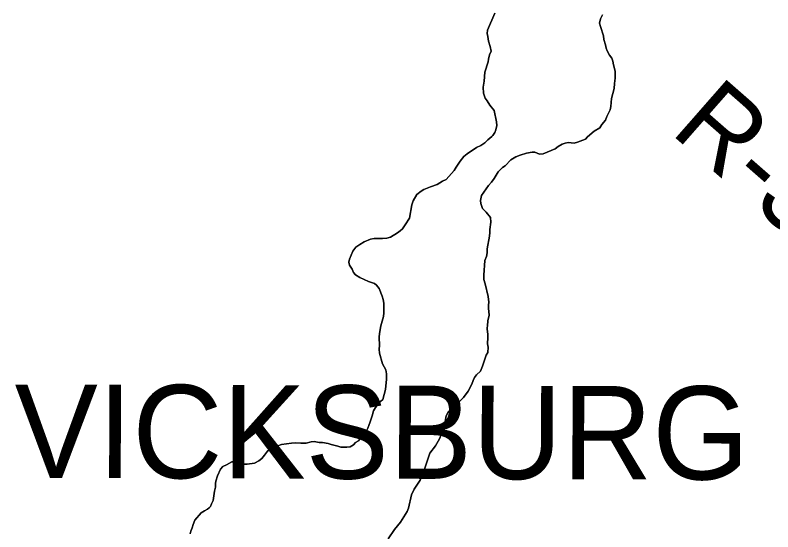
# Model space of a CAD drawing. Extents: x 3172297 to 3210190, y 958463 to 983887.
# Drawn here: x 3190075 to 3190887, y 964550 to 965104 of the extents above; entities that cross this region are included whole.
import ezdxf

# ---------------------------------------------------------------- set-up
doc = ezdxf.new("R2010")
doc.units = 0
for name, color, linetype in [('V-RIVR-RANG-IDEN', 7, 'Continuous'), ('V-SITE-VEGE', 7, 'Continuous'), ('V-TOPO-GNAM-IDEN', 7, 'Continuous'), ('V-TOPO-SHOR', 7, 'Continuous')]:
    doc.layers.add(name, color=color, linetype=linetype)

msp = doc.modelspace()

# ---------------------------------------------------------------- linework, layer by layer
at = {"layer": 'V-SITE-VEGE'}
for p, q in [((3190589.23, 965106.31), (3190581.36, 965088.03)), ((3190701.2, 965095.65), (3190702.22, 965100.13)), ((3190702.22, 965100.13), (3190704.62, 965104.62)), ((3190702.25, 965091.86), (3190701.2, 965095.65)), ((3190705.73, 965081.89), (3190702.25, 965091.86)), ((3190581.36, 965088.03), (3190581.03, 965084.58)), ((3190581.03, 965084.58), (3190581.73, 965081.14)), ((3190581.73, 965081.14), (3190582.44, 965076.32)), ((3190582.44, 965076.32), (3190584.18, 965070.47)), ((3190706.08, 965078.1), (3190705.73, 965081.89)), ((3190707.82, 965072.25), (3190706.08, 965078.1)), ((3190584.18, 965070.47), (3190585.22, 965065.65)), ((3190708.52, 965068.81), (3190707.82, 965072.25)), ((3190709.57, 965065.71), (3190708.52, 965068.81)), ((3190583.51, 965061.51), (3190582.15, 965057.03)), ((3190585.22, 965065.65), (3190583.51, 965061.51)), ((3190711.99, 965061.24), (3190709.57, 965065.71)), ((3190714.41, 965058.15), (3190711.99, 965061.24)), ((3190581.82, 965053.93), (3190578.41, 965042.89)), ((3190582.15, 965057.03), (3190581.82, 965053.93)), ((3190715.46, 965054.71), (3190714.41, 965058.15)), ((3190716.16, 965050.92), (3190715.46, 965054.71)), ((3190717.91, 965044.04), (3190716.16, 965050.92)), ((3190578.41, 965042.89), (3190577.75, 965033.25)), ((3190717.93, 965036.46), (3190717.91, 965044.04)), ((3190717.26, 965030.94), (3190717.93, 965036.46)), ((3190577.75, 965033.25), (3190576.74, 965027.05)), ((3190576.74, 965027.05), (3190577.1, 965020.5)), ((3190716.93, 965025.44), (3190717.26, 965030.94)), ((3190577.1, 965020.5), (3190578.85, 965015)), ((3190714.21, 965014.75), (3190716.93, 965025.44)), ((3190578.85, 965015), (3190580.92, 965012.25)), ((3190580.92, 965012.25), (3190583.69, 965007.43)), ((3190713.55, 965006.14), (3190714.21, 965014.75)), ((3190583.69, 965007.43), (3190588.53, 965001.94)), ((3190709.11, 964995.44), (3190712.53, 965002.69)), ((3190712.53, 965002.69), (3190713.55, 965006.14)), ((3190588.53, 965001.94), (3190590.98, 964989.89)), ((3190707.74, 964991.65), (3190709.11, 964995.44)), ((3190590.98, 964989.89), (3190591.34, 964985.76)), ((3190701.57, 964983.36), (3190703.62, 964986.81)), ((3190703.62, 964986.81), (3190707.74, 964991.65)), ((3190588.95, 964978.17), (3190586.9, 964975.07)), ((3190590.32, 964981.28), (3190588.95, 964978.17)), ((3190591.34, 964985.76), (3190590.32, 964981.28)), ((3190688.51, 964973.68), (3190695.38, 964979.9)), ((3190695.38, 964979.9), (3190701.57, 964983.36)), ((3190581.75, 964970.57), (3190578.31, 964967.12)), ((3190585.87, 964974.03), (3190581.75, 964970.57)), ((3190586.9, 964975.07), (3190585.87, 964974.03)), ((3190680.6, 964969.17), (3190686.11, 964971.26)), ((3190686.11, 964971.26), (3190688.51, 964973.68)), ((3190569.37, 964962.27), (3190559.41, 964955.34)), ((3190574.19, 964964.35), (3190569.37, 964962.27)), ((3190578.31, 964967.12), (3190574.19, 964964.35)), ((3190653.77, 964960.82), (3190656.85, 964963.24)), ((3190656.85, 964963.24), (3190661.33, 964965.66)), ((3190661.33, 964965.66), (3190664.42, 964966.71)), ((3190664.42, 964966.71), (3190667.52, 964967.41)), ((3190667.52, 964967.41), (3190674.07, 964966.74)), ((3190674.07, 964966.74), (3190677.85, 964967.79)), ((3190677.85, 964967.79), (3190680.6, 964969.17)), ((3190559.41, 964955.34), (3190555.97, 964952.58)), ((3190611.43, 964952.07), (3190616.24, 964954.15)), ((3190616.24, 964954.15), (3190623.12, 964956.24)), ((3190623.12, 964956.24), (3190628.98, 964957.29)), ((3190628.98, 964957.29), (3190632.08, 964957.3)), ((3190632.08, 964957.3), (3190636.91, 964954.91)), ((3190636.91, 964954.91), (3190641.04, 964955.61)), ((3190641.04, 964955.61), (3190653.77, 964960.82)), ((3190551.85, 964947.4), (3190547.74, 964941.18)), ((3190555.97, 964952.58), (3190551.85, 964947.4)), ((3190600.09, 964942.73), (3190606.27, 964948.95)), ((3190606.27, 964948.95), (3190611.43, 964952.07)), ((3190545.69, 964937.39), (3190537.1, 964928.06)), ((3190547.74, 964941.18), (3190545.69, 964937.39)), ((3190592.53, 964936.16), (3190597.34, 964940.66)), ((3190597.34, 964940.66), (3190600.09, 964942.73)), ((3190588.42, 964928.92), (3190592.53, 964936.16)), ((3190527.14, 964922.52), (3190520.25, 964920.08)), ((3190532.98, 964925.98), (3190527.14, 964922.52)), ((3190537.1, 964928.06), (3190532.98, 964925.98)), ((3190574.71, 964910.62), (3190582.25, 964921.32)), ((3190582.25, 964921.32), (3190585.68, 964925.12)), ((3190585.68, 964925.12), (3190588.42, 964928.92)), ((3190510.28, 964915.57), (3190505.47, 964911.77)), ((3190513.03, 964917.3), (3190510.28, 964915.57)), ((3190520.25, 964920.08), (3190513.03, 964917.3)), ((3190501.7, 964904.87), (3190500, 964900.73)), ((3190505.47, 964911.77), (3190501.7, 964904.87)), ((3190573.69, 964905.45), (3190574.71, 964910.62)), ((3190574.04, 964902.35), (3190573.69, 964905.45)), ((3190500, 964900.73), (3190497.63, 964886.6)), ((3190575.79, 964896.84), (3190574.04, 964902.35)), ((3190579.93, 964892.72), (3190575.79, 964896.84)), ((3190584.43, 964887.23), (3190579.93, 964892.72)), ((3190497.63, 964886.6), (3190493.18, 964879.35)), ((3190583.78, 964874.48), (3190584.79, 964882.06)), ((3190584.79, 964882.06), (3190584.43, 964887.23)), ((3190487.68, 964872.79), (3190484.94, 964870.71)), ((3190490.09, 964874.86), (3190487.68, 964872.79)), ((3190493.18, 964879.35), (3190490.09, 964874.86)), ((3190583.79, 964871.03), (3190583.78, 964874.48)), ((3190455.68, 964864.07), (3190449.15, 964860.95)), ((3190459.81, 964864.78), (3190455.68, 964864.07)), ((3190468.77, 964864.81), (3190459.81, 964864.78)), ((3190473.24, 964865.17), (3190468.77, 964864.81)), ((3190477.37, 964866.21), (3190473.24, 964865.17)), ((3190484.94, 964870.71), (3190477.37, 964866.21)), ((3190580.75, 964853.46), (3190583.46, 964867.24)), ((3190583.46, 964867.24), (3190583.79, 964871.03)), ((3190444.33, 964858.18), (3190440.21, 964855.41)), ((3190449.15, 964860.95), (3190444.33, 964858.18)), ((3190436.78, 964850.93), (3190433.36, 964842.65)), ((3190440.21, 964855.41), (3190436.78, 964850.93)), ((3190580.08, 964845.54), (3190580.76, 964849.33)), ((3190580.76, 964849.33), (3190580.75, 964853.46)), ((3190433.36, 964842.65), (3190432.68, 964839.2)), ((3190577.4, 964825.2), (3190578.38, 964841.05)), ((3190578.38, 964841.05), (3190580.08, 964845.54)), ((3190432.68, 964839.2), (3190433.38, 964836.1)), ((3190433.38, 964836.1), (3190436.15, 964831.63)), ((3190436.15, 964831.63), (3190437.54, 964828.19)), ((3190437.54, 964828.19), (3190439.62, 964825.79)), ((3190439.62, 964825.79), (3190444.45, 964822.71)), ((3190577.41, 964820.72), (3190577.4, 964825.2)), ((3190444.45, 964822.71), (3190453.76, 964818.6)), ((3190453.76, 964818.6), (3190459.97, 964816.55)), ((3190459.97, 964816.55), (3190462.39, 964814.49)), ((3190578.8, 964815.91), (3190577.41, 964820.72)), ((3190581.95, 964802.49), (3190578.8, 964815.91)), ((3190462.39, 964814.49), (3190465.15, 964811.06)), ((3190465.15, 964811.06), (3190468.28, 964802.8)), ((3190468.28, 964802.8), (3190469.32, 964799.36)), ((3190469.32, 964799.36), (3190470.02, 964795.23)), ((3190582.66, 964796.29), (3190581.95, 964802.49)), ((3190470.02, 964795.23), (3190470.06, 964784.9)), ((3190582.32, 964793.19), (3190582.66, 964796.29)), ((3190582.33, 964790.09), (3190582.32, 964793.19)), ((3190470.06, 964784.9), (3190469.73, 964781.11)), ((3190583.04, 964782.51), (3190582.33, 964790.09)), ((3190469.73, 964781.11), (3190467, 964771.11)), ((3190581.36, 964771.14), (3190581.69, 964776.31)), ((3190581.69, 964776.31), (3190583.04, 964782.51)), ((3190467, 964771.11), (3190465.65, 964762.84)), ((3190581.02, 964769.07), (3190581.36, 964771.14)), ((3190581.03, 964767.69), (3190581.02, 964769.07)), ((3190581.73, 964761.84), (3190581.03, 964767.69)), ((3190465.65, 964762.84), (3190465.32, 964759.05)), ((3190465.32, 964759.05), (3190465.35, 964750.1)), ((3190581.75, 964758.4), (3190581.73, 964761.84)), ((3190581.08, 964751.85), (3190581.75, 964758.4)), ((3190581.78, 964748.06), (3190581.08, 964751.85)), ((3190465.35, 964750.1), (3190465.02, 964745.96)), ((3190465.02, 964745.96), (3190465.38, 964741.83)), ((3190579.74, 964739.44), (3190581.45, 964742.55)), ((3190581.45, 964742.55), (3190581.78, 964748.06)), ((3190465.38, 964741.83), (3190468.86, 964730.48)), ((3190575.99, 964727.72), (3190579.74, 964739.44)), ((3190468.86, 964730.48), (3190472.32, 964723.94)), ((3190573.6, 964722.55), (3190575.99, 964727.72)), ((3190472.32, 964723.94), (3190473.03, 964719.47)), ((3190473.03, 964719.47), (3190473.04, 964713.95)), ((3190567.42, 964715.64), (3190569.48, 964718.4)), ((3190569.48, 964718.4), (3190573.6, 964722.55)), ((3190473.04, 964713.95), (3190472.05, 964702.93)), ((3190564.34, 964708.39), (3190565.71, 964712.53)), ((3190565.71, 964712.53), (3190567.42, 964715.64)), ((3190472.05, 964702.93), (3190470.34, 964697.41)), ((3190560.57, 964701.15), (3190564.34, 964708.39)), ((3190470.34, 964697.41), (3190468.98, 964691.9)), ((3190547.19, 964685.95), (3190555.43, 964694.24)), ((3190555.43, 964694.24), (3190560.57, 964701.15)), ((3190466.58, 964689.82), (3190461.09, 964683.6)), ((3190468.98, 964691.9), (3190466.58, 964689.82)), ((3190543.07, 964682.49), (3190547.19, 964685.95)), ((3190459.04, 964679.81), (3190457.67, 964674.64)), ((3190461.09, 964683.6), (3190459.04, 964679.81)), ((3190536.9, 964674.55), (3190539.29, 964679.04)), ((3190539.29, 964679.04), (3190543.07, 964682.49)), ((3190457.67, 964674.64), (3190455.63, 964668.09)), ((3190535.55, 964665.59), (3190536.22, 964670.76)), ((3190536.22, 964670.76), (3190536.9, 964674.55)), ((3190452.9, 964661.19), (3190449.81, 964654.98)), ((3190453.92, 964664.29), (3190452.9, 964661.19)), ((3190455.63, 964668.09), (3190453.92, 964664.29)), ((3190532.82, 964656.97), (3190534.53, 964661.8)), ((3190534.53, 964661.8), (3190535.55, 964665.59)), ((3190449.81, 964654.98), (3190443.98, 964649.1)), ((3190529.74, 964650.07), (3190531.45, 964654.21)), ((3190531.45, 964654.21), (3190532.82, 964656.97)), ((3190371.31, 964645.42), (3190360.3, 964643.66)), ((3190375.79, 964645.78), (3190371.31, 964645.42)), ((3190381.3, 964645.11), (3190375.79, 964645.78)), ((3190386.81, 964645.13), (3190381.3, 964645.11)), ((3190392.32, 964646.52), (3190386.81, 964645.13)), ((3190395.42, 964646.88), (3190392.32, 964646.52)), ((3190400.93, 964645.86), (3190395.42, 964646.88)), ((3190404.38, 964645.88), (3190400.93, 964645.86)), ((3190410.58, 964644.86), (3190404.38, 964645.88)), ((3190413.68, 964643.84), (3190410.58, 964644.86)), ((3190439.85, 964645.99), (3190437.8, 964643.57)), ((3190442.95, 964647.72), (3190439.85, 964645.99)), ((3190443.98, 964649.1), (3190442.95, 964647.72)), ((3190525.63, 964642.48), (3190529.74, 964650.07)), ((3190345.51, 964636.73), (3190342.42, 964632.24)), ((3190348.26, 964638.8), (3190345.51, 964636.73)), ((3190351.35, 964639.85), (3190348.26, 964638.8)), ((3190356.51, 964642.28), (3190351.35, 964639.85)), ((3190360.3, 964643.66), (3190356.51, 964642.28)), ((3190420.92, 964642.14), (3190413.68, 964643.84)), ((3190424.03, 964641.12), (3190420.92, 964642.14)), ((3190427.47, 964641.13), (3190424.03, 964641.12)), ((3190430.57, 964640.79), (3190427.47, 964641.13)), ((3190434.01, 964641.15), (3190430.57, 964640.79)), ((3190437.8, 964643.57), (3190434.01, 964641.15)), ((3190519.46, 964634.54), (3190525.63, 964642.48)), ((3190339.33, 964628.78), (3190336.24, 964626.37)), ((3190342.42, 964632.24), (3190339.33, 964628.78)), ((3190515.36, 964622.82), (3190519.46, 964634.54)), ((3190301.47, 964622.12), (3190297.68, 964620.38)), ((3190307.31, 964625.23), (3190301.47, 964622.12)), ((3190310.41, 964625.25), (3190307.31, 964625.23)), ((3190315.24, 964624.23), (3190310.41, 964625.25)), ((3190319.38, 964622.87), (3190315.24, 964624.23)), ((3190323.85, 964622.88), (3190319.38, 964622.87)), ((3190331.43, 964623.94), (3190323.85, 964622.88)), ((3190336.24, 964626.37), (3190331.43, 964623.94)), ((3190512.3, 964612.81), (3190515.36, 964622.82)), ((3190294.94, 964617.28), (3190291.86, 964610.38)), ((3190297.68, 964620.38), (3190294.94, 964617.28)), ((3190510.93, 964609.36), (3190512.3, 964612.81)), ((3190290.16, 964604.52), (3190289.82, 964602.1)), ((3190291.86, 964610.38), (3190290.16, 964604.52)), ((3190502.71, 964595.91), (3190509.22, 964605.57)), ((3190509.22, 964605.57), (3190510.93, 964609.36)), ((3190289.83, 964597.97), (3190288.81, 964593.83)), ((3190289.82, 964602.1), (3190289.83, 964597.97)), ((3190288.81, 964593.83), (3190287.12, 964583.84)), ((3190496.57, 964575.56), (3190499.97, 964590.04)), ((3190499.97, 964590.04), (3190502.71, 964595.91)), ((3190285.41, 964580.39), (3190284.39, 964577.29)), ((3190287.12, 964583.84), (3190285.41, 964580.39)), ((3190277.86, 964572.79), (3190274.42, 964570.71)), ((3190281.3, 964574.52), (3190277.86, 964572.79)), ((3190283.02, 964575.9), (3190281.3, 964574.52)), ((3190284.39, 964577.29), (3190283.02, 964575.9)), ((3190488.01, 964560.72), (3190495.21, 964572.11)), ((3190495.21, 964572.11), (3190496.57, 964575.56)), ((3190274.42, 964570.71), (3190267.56, 964562.76)), ((3190265.85, 964557.94), (3190264.83, 964554.49)), ((3190267.56, 964562.76), (3190265.85, 964557.94)), ((3190481.49, 964552.78), (3190484.92, 964556.58)), ((3190484.92, 964556.58), (3190488.01, 964560.72)), ((3190263.46, 964551.04), (3190262.44, 964547.94)), ((3190264.83, 964554.49), (3190263.46, 964551.04)), ((3190474.63, 964542.77), (3190481.49, 964552.78))]:
    msp.add_line(p, q, dxfattribs=at)
at = {"layer": 'V-TOPO-SHOR'}
for points in [[(3190582.15, 965057.03), (3190583.51, 965061.51), (3190585.22, 965065.65), (3190584.18, 965070.47), (3190582.44, 965076.32), (3190581.73, 965081.14), (3190581.03, 965084.58), (3190581.36, 965088.03), (3190589.23, 965106.31)], [(3190704.62, 965104.62), (3190702.22, 965100.13), (3190701.2, 965095.65), (3190702.25, 965091.86), (3190705.73, 965081.89), (3190706.08, 965078.1), (3190707.82, 965072.25), (3190708.52, 965068.81), (3190709.57, 965065.71), (3190711.99, 965061.24), (3190714.41, 965058.15), (3190715.46, 965054.71), (3190716.16, 965050.92), (3190717.91, 965044.04), (3190717.93, 965036.46), (3190717.26, 965030.95), (3190716.93, 965025.44), (3190714.21, 965014.75), (3190713.55, 965006.14), (3190712.53, 965002.69), (3190709.11, 964995.44), (3190707.74, 964991.65), (3190703.62, 964986.81), (3190701.57, 964983.36), (3190695.38, 964979.9), (3190688.51, 964973.68), (3190686.11, 964971.26), (3190680.6, 964969.17), (3190677.85, 964967.79), (3190674.07, 964966.74), (3190667.52, 964967.41)], [(3190386.81, 964645.13), (3190392.32, 964646.52), (3190395.42, 964646.88), (3190400.93, 964645.86), (3190404.38, 964645.88), (3190410.58, 964644.86), (3190413.68, 964643.84), (3190420.92, 964642.14), (3190424.03, 964641.12), (3190427.47, 964641.13), (3190430.57, 964640.79), (3190434.01, 964641.15), (3190437.8, 964643.57), (3190439.85, 964645.99), (3190442.95, 964647.72), (3190443.98, 964649.1), (3190449.81, 964654.98), (3190452.9, 964661.19), (3190453.92, 964664.29), (3190455.63, 964668.09), (3190457.67, 964674.64), (3190459.04, 964679.81), (3190461.09, 964683.6), (3190466.58, 964689.82), (3190468.98, 964691.9), (3190470.34, 964697.41), (3190472.05, 964702.93), (3190473.04, 964713.95), (3190473.03, 964719.47), (3190472.32, 964723.94), (3190468.86, 964730.47), (3190465.38, 964741.83), (3190465.02, 964745.96), (3190465.35, 964750.1), (3190465.32, 964759.05), (3190465.65, 964762.84), (3190467, 964771.11), (3190469.73, 964781.11), (3190470.06, 964784.9), (3190470.02, 964795.23), (3190469.32, 964799.36), (3190468.28, 964802.8), (3190465.15, 964811.06), (3190462.39, 964814.49), (3190459.97, 964816.55), (3190453.76, 964818.6), (3190444.45, 964822.71), (3190439.62, 964825.79), (3190437.54, 964828.19), (3190436.15, 964831.63), (3190433.38, 964836.1), (3190432.68, 964839.2), (3190433.36, 964842.65), (3190436.78, 964850.93), (3190440.21, 964855.41), (3190444.33, 964858.18), (3190449.15, 964860.95), (3190455.68, 964864.07), (3190459.81, 964864.78), (3190468.77, 964864.81), (3190473.24, 964865.17), (3190477.37, 964866.21), (3190484.94, 964870.71), (3190487.68, 964872.79), (3190490.09, 964874.86), (3190493.18, 964879.35), (3190497.63, 964886.6), (3190500, 964900.73), (3190501.7, 964904.87), (3190505.47, 964911.77), (3190510.28, 964915.57), (3190513.03, 964917.3), (3190520.25, 964920.08), (3190527.14, 964922.52), (3190532.98, 964925.98), (3190537.1, 964928.06), (3190545.69, 964937.39), (3190547.74, 964941.18), (3190551.85, 964947.4), (3190555.97, 964952.58), (3190559.41, 964955.34), (3190569.37, 964962.27), (3190574.19, 964964.35), (3190578.31, 964967.12), (3190581.75, 964970.57), (3190585.87, 964974.03), (3190586.9, 964975.07), (3190588.95, 964978.17), (3190590.32, 964981.28), (3190591.34, 964985.76), (3190590.98, 964989.89), (3190588.53, 965001.94), (3190583.69, 965007.43), (3190580.92, 965012.25), (3190578.85, 965015), (3190577.1, 965020.5), (3190576.74, 965027.05), (3190577.75, 965033.25), (3190578.41, 965042.89), (3190581.82, 965053.93), (3190582.15, 965057.03)], [(3190667.52, 964967.41), (3190664.42, 964966.71), (3190661.33, 964965.66), (3190656.85, 964963.24), (3190653.77, 964960.82), (3190641.04, 964955.61), (3190636.91, 964954.91), (3190632.08, 964957.3), (3190628.98, 964957.29), (3190623.12, 964956.24), (3190616.24, 964954.15), (3190611.43, 964952.07), (3190606.27, 964948.95), (3190600.09, 964942.73), (3190597.34, 964940.66), (3190592.53, 964936.16), (3190588.42, 964928.92), (3190585.68, 964925.12), (3190582.25, 964921.32), (3190574.71, 964910.62), (3190573.69, 964905.45), (3190574.04, 964902.35), (3190575.79, 964896.84), (3190579.93, 964892.72), (3190584.43, 964887.23), (3190584.79, 964882.06), (3190583.78, 964874.48), (3190583.79, 964871.03), (3190583.46, 964867.24), (3190580.75, 964853.46), (3190580.76, 964849.33), (3190580.08, 964845.54), (3190578.38, 964841.05), (3190577.4, 964825.2), (3190577.41, 964820.72), (3190578.8, 964815.91), (3190581.95, 964802.49), (3190582.66, 964796.29), (3190582.32, 964793.19), (3190582.33, 964790.08), (3190583.04, 964782.51), (3190581.69, 964776.31), (3190581.36, 964771.14), (3190581.02, 964769.07), (3190581.03, 964767.69), (3190581.73, 964761.84), (3190581.75, 964758.4), (3190581.08, 964751.85), (3190581.78, 964748.06), (3190581.45, 964742.55), (3190579.74, 964739.44), (3190575.99, 964727.72), (3190573.6, 964722.55), (3190569.48, 964718.4), (3190567.42, 964715.64), (3190565.71, 964712.53), (3190564.34, 964708.39), (3190560.57, 964701.15), (3190555.43, 964694.24), (3190547.19, 964685.95), (3190543.07, 964682.49), (3190539.29, 964679.04), (3190536.9, 964674.55), (3190536.22, 964670.76), (3190535.55, 964665.59), (3190534.53, 964661.8), (3190532.82, 964656.97), (3190531.45, 964654.21), (3190529.74, 964650.07), (3190525.63, 964642.48), (3190519.46, 964634.54), (3190515.36, 964622.82), (3190512.3, 964612.81), (3190510.93, 964609.36), (3190509.22, 964605.57), (3190502.71, 964595.91), (3190499.97, 964590.04), (3190496.57, 964575.56), (3190495.21, 964572.11), (3190488.01, 964560.72), (3190484.92, 964556.58), (3190481.49, 964552.78), (3190474.63, 964542.77)], [(3190262.44, 964547.94), (3190263.46, 964551.04), (3190264.83, 964554.49), (3190265.85, 964557.94), (3190267.56, 964562.76), (3190274.42, 964570.71), (3190277.86, 964572.79), (3190281.3, 964574.52), (3190283.02, 964575.9), (3190284.39, 964577.29), (3190285.41, 964580.39), (3190287.12, 964583.84), (3190288.81, 964593.83), (3190289.83, 964597.97), (3190289.82, 964602.1), (3190290.16, 964604.52), (3190291.86, 964610.38), (3190294.94, 964617.28), (3190297.68, 964620.38), (3190301.47, 964622.12), (3190307.31, 964625.24), (3190310.41, 964625.25), (3190315.24, 964624.23), (3190319.38, 964622.87), (3190323.85, 964622.88), (3190331.43, 964623.94), (3190336.24, 964626.37), (3190339.33, 964628.79), (3190342.42, 964632.24), (3190345.51, 964636.73), (3190348.26, 964638.8), (3190351.35, 964639.85), (3190356.51, 964642.28), (3190360.3, 964643.66), (3190371.31, 964645.42), (3190375.79, 964645.78), (3190381.3, 964645.11), (3190386.81, 964645.13)]]:
    msp.add_lwpolyline(points, dxfattribs=at)

# ---------------------------------------------------------------- texts
at = {"layer": 'V-RIVR-RANG-IDEN'}
msp.add_text('R-317.6', height=83, rotation=318.76978, dxfattribs=at).set_placement((3190775.91, 964978.3))
at = {"layer": 'V-TOPO-GNAM-IDEN'}
msp.add_text('VICKSBURG', height=100, rotation=359.85832, dxfattribs=at).set_placement((3190074.19, 964608.09))

doc.saveas('drawing.dxf')
